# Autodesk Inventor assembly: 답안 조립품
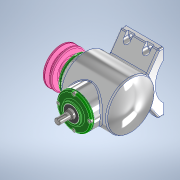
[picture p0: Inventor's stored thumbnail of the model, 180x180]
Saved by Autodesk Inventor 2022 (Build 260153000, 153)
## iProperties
Created: 2023-04
Part Number: 답안 조립품
Document SubType Name: Assembly
Designer: Admin
Author: Admin
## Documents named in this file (17)
- C:\Users\Admin\Desktop\730411V1019\답안 조립품.iam
- C:\Users\Admin\Desktop\730411V1019\본체.ipt
- C:\Users\Admin\Desktop\730411V1019\커버.ipt
- C:\Users\Admin\Desktop\730411V1019\베어링 6203.ipt
- C:\Users\Admin\Desktop\730411V1019\오일실 17 x 32 x 8.ipt
- C:\Users\Admin\Desktop\730411V1019\메인 축.ipt
- 메인 축.ipt
- C:\Users\Admin\Desktop\730411V1019\키 5 x 5 x 14.ipt
- C:\Users\Admin\Desktop\730411V1019\메인 베벨기어.ipt
- C:\Users\Admin\Desktop\730411V1019\서브 축.ipt
- 서브 축.ipt
- C:\Users\Admin\Desktop\730411V1019\키 4 x 4 x 14.ipt
- C:\Users\Admin\Desktop\730411V1019\서브 베벨기어.ipt
- C:\Users\Admin\Desktop\730411V1019\V-벨트풀리.ipt
- C:\Users\Admin\Desktop\730411V1019\볼트 M4 x 10.ipt
- C:\Users\Admin\Desktop\730411V1019\와셔 4 x 16.ipt
- C:\Users\Admin\Desktop\730411V1019\육각볼트 M4 x 8.ipt
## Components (1 placed, 1 different names)
1. V-벨트풀리:1
